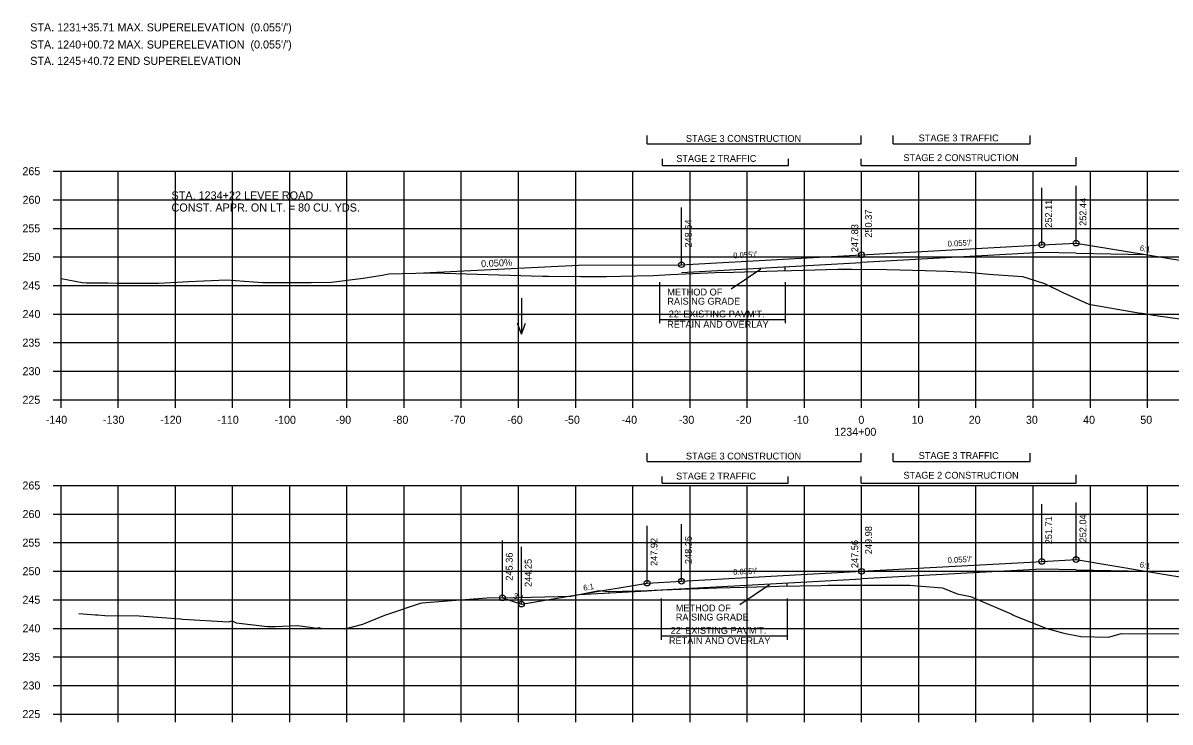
# Model space of a CAD drawing. Extents: x 1342547 to 1344156, y -1532351 to -1517216.
# Drawn here: x 1342556.2 to 1342756.8, y -1529717.5 to -1529595.1 of the extents above; entities that cross this region are included whole.
import ezdxf

# ---------------------------------------------------------------- set-up
doc = ezdxf.new("R2010")
doc.units = 0
for name, color, linetype in [('R_Alt Surface', 7, 'Continuous'), ('R_Axis', 7, 'Continuous'), ('R_Axis Annot', 7, 'Continuous'), ('R_Border Notes', 7, 'Continuous'), ('R_Draft', 7, 'Continuous'), ('R_Drive', 7, 'Continuous'), ('R_Exist Surface', 7, 'Continuous'), ('R_Fin Surface', 7, 'Continuous'), ('R_Grid', 7, 'Continuous'), ('R_No Plot', 7, 'Continuous'), ('R_Water', 7, 'Continuous'), ('R_Xsect Elev', 7, 'Continuous'), ('R_Xsect Slope', 7, 'Continuous')]:
    doc.layers.add(name, color=color, linetype=linetype)

msp = doc.modelspace()

# ---------------------------------------------------------------- linework, layer by layer
at = {"layer": 'R_Alt Surface'}
for points in [[(1342740.37, -1529635.44), (1342734.37, -1529635.32), (1342702.87, -1529637.05)], [(1342740.37, -1529635.44), (1342752.52, -1529635.68)], [(1342671.37, -1529638.79), (1342702.87, -1529637.05)], [(1342740.37, -1529690.83), (1342734.37, -1529690.71), (1342702.87, -1529692.45)], [(1342740.37, -1529690.83), (1342752.52, -1529691.08)], [(1342667.83, -1529694.37), (1342702.87, -1529692.45)], [(1342653.42, -1529695.16), (1342665.37, -1529694.51)], [(1342665.37, -1529694.51), (1342667.83, -1529694.37)]]:
    msp.add_lwpolyline(points, dxfattribs=at)
at = {"layer": 'R_Axis'}
for p, q in [((1342561.47, -1529621.09), (1342562.87, -1529621.09)), ((1342562.87, -1529661.09), (1342562.87, -1529621.09)), ((1342561.47, -1529626.09), (1342562.87, -1529626.09)), ((1342561.47, -1529631.09), (1342562.87, -1529631.09)), ((1342561.47, -1529636.09), (1342562.87, -1529636.09)), ((1342561.47, -1529641.09), (1342562.87, -1529641.09)), ((1342561.47, -1529646.09), (1342562.87, -1529646.09)), ((1342561.47, -1529651.09), (1342562.87, -1529651.09)), ((1342561.47, -1529656.09), (1342562.87, -1529656.09)), ((1342561.47, -1529661.09), (1342562.87, -1529661.09)), ((1342562.87, -1529661.09), (1342842.87, -1529661.09)), ((1342562.87, -1529662.49), (1342562.87, -1529661.09)), ((1342572.87, -1529662.49), (1342572.87, -1529661.09)), ((1342582.87, -1529662.49), (1342582.87, -1529661.09)), ((1342592.87, -1529662.49), (1342592.87, -1529661.09)), ((1342602.87, -1529662.49), (1342602.87, -1529661.09)), ((1342612.87, -1529662.49), (1342612.87, -1529661.09)), ((1342622.87, -1529662.49), (1342622.87, -1529661.09)), ((1342632.87, -1529662.49), (1342632.87, -1529661.09)), ((1342642.87, -1529662.49), (1342642.87, -1529661.09)), ((1342652.87, -1529662.49), (1342652.87, -1529661.09)), ((1342662.87, -1529662.49), (1342662.87, -1529661.09)), ((1342672.87, -1529662.49), (1342672.87, -1529661.09)), ((1342682.87, -1529662.49), (1342682.87, -1529661.09)), ((1342692.87, -1529662.49), (1342692.87, -1529661.09)), ((1342702.87, -1529662.49), (1342702.87, -1529661.09)), ((1342712.87, -1529662.49), (1342712.87, -1529661.09)), ((1342722.87, -1529662.49), (1342722.87, -1529661.09)), ((1342732.87, -1529662.49), (1342732.87, -1529661.09)), ((1342742.87, -1529662.49), (1342742.87, -1529661.09)), ((1342752.87, -1529662.49), (1342752.87, -1529661.09)), ((1342561.47, -1529676.09), (1342562.87, -1529676.09)), ((1342562.87, -1529716.09), (1342562.87, -1529676.09)), ((1342561.47, -1529681.09), (1342562.87, -1529681.09)), ((1342561.47, -1529686.09), (1342562.87, -1529686.09)), ((1342561.47, -1529691.09), (1342562.87, -1529691.09)), ((1342561.47, -1529696.09), (1342562.87, -1529696.09)), ((1342561.47, -1529701.09), (1342562.87, -1529701.09)), ((1342561.47, -1529706.09), (1342562.87, -1529706.09)), ((1342561.47, -1529711.09), (1342562.87, -1529711.09)), ((1342561.47, -1529716.09), (1342562.87, -1529716.09)), ((1342562.87, -1529716.09), (1342842.87, -1529716.09)), ((1342562.87, -1529717.49), (1342562.87, -1529716.09)), ((1342572.87, -1529717.49), (1342572.87, -1529716.09)), ((1342582.87, -1529717.49), (1342582.87, -1529716.09)), ((1342592.87, -1529717.49), (1342592.87, -1529716.09)), ((1342602.87, -1529717.49), (1342602.87, -1529716.09)), ((1342612.87, -1529717.49), (1342612.87, -1529716.09)), ((1342622.87, -1529717.49), (1342622.87, -1529716.09)), ((1342632.87, -1529717.49), (1342632.87, -1529716.09)), ((1342642.87, -1529717.49), (1342642.87, -1529716.09)), ((1342652.87, -1529717.49), (1342652.87, -1529716.09)), ((1342662.87, -1529717.49), (1342662.87, -1529716.09)), ((1342672.87, -1529717.49), (1342672.87, -1529716.09)), ((1342682.87, -1529717.49), (1342682.87, -1529716.09)), ((1342692.87, -1529717.49), (1342692.87, -1529716.09)), ((1342702.87, -1529717.49), (1342702.87, -1529716.09)), ((1342712.87, -1529717.49), (1342712.87, -1529716.09)), ((1342722.87, -1529717.49), (1342722.87, -1529716.09)), ((1342732.87, -1529717.49), (1342732.87, -1529716.09)), ((1342742.87, -1529717.49), (1342742.87, -1529716.09)), ((1342752.87, -1529717.49), (1342752.87, -1529716.09))]:
    msp.add_line(p, q, dxfattribs=at)
at = {"layer": 'R_Draft'}
for p, q in [((1342665.37, -1529616.28), (1342665.37, -1529614.85)), ((1342702.78, -1529616.28), (1342702.78, -1529614.85)), ((1342708.37, -1529616.28), (1342708.37, -1529614.85)), ((1342732.37, -1529616.28), (1342732.37, -1529614.85)), ((1342665.37, -1529616.28), (1342702.78, -1529616.28)), ((1342708.37, -1529616.28), (1342732.37, -1529616.28)), ((1342668.06, -1529620.08), (1342668.06, -1529618.93)), ((1342690.06, -1529620.08), (1342690.06, -1529618.93)), ((1342702.78, -1529620.08), (1342702.78, -1529618.93)), ((1342740.38, -1529620.08), (1342740.38, -1529618.65)), ((1342668.06, -1529620.08), (1342690.06, -1529620.08)), ((1342702.78, -1529620.08), (1342740.38, -1529620.08)), ((1342689.51, -1529638.48), (1342689.51, -1529637.79)), ((1342667.51, -1529640.51), (1342667.51, -1529647.71)), ((1342689.51, -1529640.51), (1342689.51, -1529647.71)), ((1342667.51, -1529647.04), (1342689.51, -1529647.04)), ((1342665.37, -1529671.87), (1342665.37, -1529670.44)), ((1342702.78, -1529671.87), (1342702.78, -1529670.44)), ((1342708.37, -1529671.87), (1342708.37, -1529670.44)), ((1342732.37, -1529671.87), (1342732.37, -1529670.44)), ((1342665.37, -1529671.87), (1342702.78, -1529671.87)), ((1342708.37, -1529671.87), (1342732.37, -1529671.87)), ((1342668.02, -1529675.66), (1342668.02, -1529674.52)), ((1342690.02, -1529675.66), (1342690.02, -1529674.52)), ((1342702.78, -1529675.66), (1342702.78, -1529674.52)), ((1342740.38, -1529675.66), (1342740.38, -1529674.23)), ((1342668.02, -1529675.66), (1342690.02, -1529675.66)), ((1342702.78, -1529675.66), (1342740.38, -1529675.66)), ((1342689.83, -1529693.68), (1342689.83, -1529693.16)), ((1342667.83, -1529695.89), (1342667.83, -1529703.09)), ((1342689.83, -1529695.89), (1342689.83, -1529703.09)), ((1342667.83, -1529702.41), (1342689.83, -1529702.41))]:
    msp.add_line(p, q, dxfattribs=at)
at = {"layer": 'R_Drive'}
msp.add_lwpolyline([(1342626.25, -1529638.89), (1342653.37, -1529637.52), (1342671.37, -1529637.45)], dxfattribs=at)
at = {"layer": 'R_Exist Surface'}
for points in [[(1342562.87, -1529639.85), (1342566.56, -1529640.54), (1342567.34, -1529640.61), (1342571.07, -1529640.62), (1342572.71, -1529640.67), (1342579.92, -1529640.66), (1342585.23, -1529640.39), (1342591.78, -1529640.11), (1342598.13, -1529640.57), (1342602.21, -1529640.58), (1342606.61, -1529640.59), (1342610.14, -1529640.49), (1342615.73, -1529639.81), (1342619.03, -1529639.26), (1342620.17, -1529639.04), (1342627.26, -1529638.86), (1342627.48, -1529638.86), (1342627.6, -1529638.86), (1342629.91, -1529638.93), (1342647.06, -1529639.44), (1342647.41, -1529639.45), (1342647.52, -1529639.44), (1342648.11, -1529639.45), (1342653.79, -1529639.52), (1342656.73, -1529639.52), (1342658.27, -1529639.53), (1342660.79, -1529639.47), (1342666.39, -1529639.34), (1342669.45, -1529639.19), (1342677.24, -1529638.84), (1342680.48, -1529638.74), (1342688.16, -1529638.51), (1342690.6, -1529638.45), (1342696.73, -1529638.27), (1342698.72, -1529638.24), (1342701.15, -1529638.25), (1342707.29, -1529638.31), (1342714.01, -1529638.44), (1342717.84, -1529638.59), (1342721.4, -1529638.76), (1342725.13, -1529639.11), (1342731.01, -1529639.54), (1342731.92, -1529639.82), (1342734.87, -1529640.75), (1342738.07, -1529642.31), (1342742.61, -1529644.38), (1342751.27, -1529645.85), (1342751.95, -1529645.96), (1342753.89, -1529646.28), (1342759.34, -1529647.03)], [(1342565.98, -1529698.5), (1342568.91, -1529698.71), (1342569.32, -1529698.72), (1342570.55, -1529698.86), (1342576.55, -1529698.89), (1342583.77, -1529699.45), (1342583.82, -1529699.45), (1342584.17, -1529699.48), (1342592.14, -1529699.95), (1342592.78, -1529699.78), (1342593.49, -1529700.15), (1342598.96, -1529700.77), (1342600.29, -1529700.75), (1342604.18, -1529700.62), (1342606.46, -1529700.89), (1342607.46, -1529701.04), (1342608.04, -1529700.95), (1342608.49, -1529701.19), (1342609.24, -1529701.09), (1342612.48, -1529701.17), (1342615.64, -1529700.33), (1342619.47, -1529698.76), (1342625.75, -1529696.71), (1342626.04, -1529696.6), (1342627.45, -1529696.52), (1342637.31, -1529695.77), (1342642.77, -1529695.7), (1342649.8, -1529695.54), (1342652.04, -1529695.45), (1342656.97, -1529694.48), (1342658.53, -1529694.62), (1342658.77, -1529694.67), (1342665.49, -1529694.46), (1342666.62, -1529694.43), (1342668.13, -1529694.36), (1342677.62, -1529694), (1342686.87, -1529693.75), (1342688.4, -1529693.71), (1342695.8, -1529693.57), (1342696.97, -1529693.54), (1342697.35, -1529693.54), (1342700.77, -1529693.54), (1342709.1, -1529693.53), (1342711.29, -1529693.51), (1342712.61, -1529693.65), (1342717.03, -1529694.01), (1342719.57, -1529695.06), (1342721.89, -1529695.52), (1342729.11, -1529698.63), (1342729.33, -1529698.74), (1342729.42, -1529698.78), (1342729.67, -1529698.88), (1342735.27, -1529701.12), (1342738.22, -1529701.96), (1342741.2, -1529702.54), (1342746.05, -1529702.62), (1342748.3, -1529702.02), (1342760.21, -1529702.06)]]:
    msp.add_lwpolyline(points, dxfattribs=at)
at = {"layer": 'R_Fin Surface'}
for points in [[(1342671.37, -1529637.45), (1342673.37, -1529637.34), (1342702.87, -1529635.72), (1342732.37, -1529634.1), (1342734.37, -1529633.99), (1342740.37, -1529633.66), (1342752.52, -1529635.68), (1342762.37, -1529637.32), (1342795.4, -1529648.34)], [(1342640.05, -1529695.74), (1342643.37, -1529696.84), (1342653.42, -1529695.16), (1342665.37, -1529693.17), (1342671.37, -1529692.84), (1342673.37, -1529692.73), (1342702.87, -1529691.11), (1342732.37, -1529689.49), (1342734.37, -1529689.38), (1342740.37, -1529689.05), (1342752.52, -1529691.08), (1342762.37, -1529692.72), (1342792.84, -1529702.87)]]:
    msp.add_lwpolyline(points, dxfattribs=at)
at = {"layer": 'R_Grid'}
for p, q in [((1342562.87, -1529621.09), (1342842.87, -1529621.09)), ((1342562.87, -1529661.09), (1342562.87, -1529621.09)), ((1342572.87, -1529661.09), (1342572.87, -1529621.09)), ((1342582.87, -1529661.09), (1342582.87, -1529621.09)), ((1342592.87, -1529661.09), (1342592.87, -1529621.09)), ((1342602.87, -1529661.09), (1342602.87, -1529621.09)), ((1342612.87, -1529661.09), (1342612.87, -1529621.09)), ((1342622.87, -1529661.09), (1342622.87, -1529621.09)), ((1342632.87, -1529661.09), (1342632.87, -1529621.09)), ((1342642.87, -1529661.09), (1342642.87, -1529621.09)), ((1342652.87, -1529661.09), (1342652.87, -1529621.09)), ((1342662.87, -1529661.09), (1342662.87, -1529621.09)), ((1342672.87, -1529661.09), (1342672.87, -1529621.09)), ((1342682.87, -1529661.09), (1342682.87, -1529621.09)), ((1342692.87, -1529661.09), (1342692.87, -1529621.09)), ((1342702.87, -1529661.09), (1342702.87, -1529621.09)), ((1342712.87, -1529661.09), (1342712.87, -1529621.09)), ((1342722.87, -1529661.09), (1342722.87, -1529621.09)), ((1342732.87, -1529661.09), (1342732.87, -1529621.09)), ((1342742.87, -1529661.09), (1342742.87, -1529621.09)), ((1342752.87, -1529661.09), (1342752.87, -1529621.09)), ((1342562.87, -1529626.09), (1342842.87, -1529626.09)), ((1342562.87, -1529631.09), (1342842.87, -1529631.09)), ((1342562.87, -1529636.09), (1342842.87, -1529636.09)), ((1342562.87, -1529641.09), (1342842.87, -1529641.09)), ((1342562.87, -1529646.09), (1342842.87, -1529646.09)), ((1342562.87, -1529651.09), (1342842.87, -1529651.09)), ((1342562.87, -1529656.09), (1342842.87, -1529656.09)), ((1342562.87, -1529661.09), (1342842.87, -1529661.09)), ((1342562.87, -1529676.09), (1342842.87, -1529676.09)), ((1342562.87, -1529716.09), (1342562.87, -1529676.09)), ((1342572.87, -1529716.09), (1342572.87, -1529676.09)), ((1342582.87, -1529716.09), (1342582.87, -1529676.09)), ((1342592.87, -1529716.09), (1342592.87, -1529676.09)), ((1342602.87, -1529716.09), (1342602.87, -1529676.09)), ((1342612.87, -1529716.09), (1342612.87, -1529676.09)), ((1342622.87, -1529716.09), (1342622.87, -1529676.09)), ((1342632.87, -1529716.09), (1342632.87, -1529676.09)), ((1342642.87, -1529716.09), (1342642.87, -1529676.09)), ((1342652.87, -1529716.09), (1342652.87, -1529676.09)), ((1342662.87, -1529716.09), (1342662.87, -1529676.09)), ((1342672.87, -1529716.09), (1342672.87, -1529676.09)), ((1342682.87, -1529716.09), (1342682.87, -1529676.09)), ((1342692.87, -1529716.09), (1342692.87, -1529676.09)), ((1342702.87, -1529716.09), (1342702.87, -1529676.09)), ((1342712.87, -1529716.09), (1342712.87, -1529676.09)), ((1342722.87, -1529716.09), (1342722.87, -1529676.09)), ((1342732.87, -1529716.09), (1342732.87, -1529676.09)), ((1342742.87, -1529716.09), (1342742.87, -1529676.09)), ((1342752.87, -1529716.09), (1342752.87, -1529676.09)), ((1342562.87, -1529681.09), (1342842.87, -1529681.09)), ((1342562.87, -1529686.09), (1342842.87, -1529686.09)), ((1342562.87, -1529691.09), (1342842.87, -1529691.09)), ((1342562.87, -1529696.09), (1342842.87, -1529696.09)), ((1342562.87, -1529701.09), (1342842.87, -1529701.09)), ((1342562.87, -1529706.09), (1342842.87, -1529706.09)), ((1342562.87, -1529711.09), (1342842.87, -1529711.09)), ((1342562.87, -1529716.09), (1342842.87, -1529716.09))]:
    msp.add_line(p, q, dxfattribs=at)
at = {"layer": 'R_No Plot'}
for centre in [(1342734.37, -1529633.99), (1342740.37, -1529633.66), (1342671.37, -1529637.45), (1342702.87, -1529635.72), (1342734.37, -1529689.38), (1342740.37, -1529689.05), (1342702.87, -1529691.11), (1342665.37, -1529693.17), (1342671.37, -1529692.84), (1342640.05, -1529695.74), (1342643.37, -1529696.84)]:
    msp.add_circle(centre, 0.5, dxfattribs=at)
at = {"layer": 'R_Water'}
for p, q in [((1342643.42, -1529643.33), (1342643.42, -1529649.62)), ((1342643.42, -1529649.62), (1342642.72, -1529647.69)), ((1342643.42, -1529649.62), (1342644.12, -1529647.69))]:
    msp.add_line(p, q, dxfattribs=at)
at = {"layer": 'R_Xsect Elev'}
for p, q in [((1342734.37, -1529633.99), (1342734.37, -1529623.99)), ((1342740.37, -1529633.66), (1342740.37, -1529623.66)), ((1342702.87, -1529635.72), (1342702.87, -1529625.72)), ((1342671.37, -1529637.45), (1342671.37, -1529627.45)), ((1342702.87, -1529638.26), (1342702.87, -1529628.26)), ((1342685.26, -1529638.22), (1342680.06, -1529641.71)), ((1342740.37, -1529689.05), (1342740.37, -1529679.05)), ((1342702.87, -1529691.11), (1342702.87, -1529681.11)), ((1342734.37, -1529689.38), (1342734.37, -1529679.38)), ((1342671.37, -1529692.84), (1342671.37, -1529682.84)), ((1342665.37, -1529693.17), (1342665.37, -1529683.17)), ((1342702.87, -1529693.54), (1342702.87, -1529683.54)), ((1342640.05, -1529695.74), (1342640.05, -1529685.74)), ((1342643.37, -1529696.84), (1342643.37, -1529686.84)), ((1342686.75, -1529693.5), (1342681.55, -1529696.98))]:
    msp.add_line(p, q, dxfattribs=at)

# ---------------------------------------------------------------- texts
at = {"layer": 'R_Axis Annot'}
for s, p in [('265', (1342556.12, -1529621.79)), ('260', (1342556.14, -1529626.79)), ('255', (1342556.12, -1529631.79)), ('250', (1342556.14, -1529636.79)), ('245', (1342556.12, -1529641.79)), ('240', (1342556.14, -1529646.79)), ('235', (1342556.12, -1529651.79)), ('230', (1342556.14, -1529656.79)), ('225', (1342556.12, -1529661.79)), ('-140', (1342560.2, -1529665.29)), ('-130', (1342570.2, -1529665.29)), ('-120', (1342580.2, -1529665.29)), ('-110', (1342590.2, -1529665.29)), ('-100', (1342600.2, -1529665.29)), ('-90', (1342610.9, -1529665.29)), ('-80', (1342620.9, -1529665.29)), ('-70', (1342630.9, -1529665.29)), ('-60', (1342640.9, -1529665.29)), ('-50', (1342650.9, -1529665.29)), ('-40', (1342660.9, -1529665.29)), ('-30', (1342670.9, -1529665.29)), ('-20', (1342680.9, -1529665.29)), ('-10', (1342690.9, -1529665.29)), ('0', (1342702.3, -1529665.29)), ('10', (1342711.6, -1529665.29)), ('20', (1342721.6, -1529665.29)), ('30', (1342731.6, -1529665.29)), ('40', (1342741.6, -1529665.29)), ('50', (1342751.6, -1529665.29)), ('1234+00', (1342698.1, -1529667.39)), ('265', (1342556.12, -1529676.79)), ('260', (1342556.14, -1529681.79)), ('255', (1342556.12, -1529686.79)), ('250', (1342556.14, -1529691.79)), ('245', (1342556.12, -1529696.79)), ('240', (1342556.14, -1529701.79)), ('235', (1342556.12, -1529706.79)), ('230', (1342556.14, -1529711.79)), ('225', (1342556.12, -1529716.79))]:
    msp.add_text(s, height=1.4, dxfattribs=at).set_placement(p)
at = {"layer": 'R_Border Notes'}
for s, height, p in [("STA. 1231+35.71 MAX. SUPERELEVATION  (0.055'/')", 1.41, (1342557.48, -1529596.62)), ("STA. 1240+00.72 MAX. SUPERELEVATION  (0.055'/')", 1.41, (1342557.48, -1529599.62)), ('STA. 1245+40.72 END SUPERELEVATION', 1.41, (1342557.48, -1529602.48)), ('STA. 1234+22 LEVEE ROAD', 1.4147, (1342582.19, -1529626.03)), ('CONST. APPR. ON LT. = 80 CU. YDS.', 1.4147, (1342582.19, -1529628.15))]:
    msp.add_text(s, height=height, dxfattribs=at).set_placement(p)
at = {"layer": 'R_Draft'}
for s, p in [('STAGE 3 CONSTRUCTION', (1342672.14, -1529615.96)), ('STAGE 3 TRAFFIC', (1342712.85, -1529615.87)), ('STAGE 2 TRAFFIC', (1342670.46, -1529619.45)), ('STAGE 2 CONSTRUCTION', (1342710.18, -1529619.32)), ("22' EXISTING PAVM'T.", (1342669.15, -1529646.67)), ('RETAIN AND OVERLAY', (1342668.86, -1529648.47)), ('STAGE 3 CONSTRUCTION', (1342672.14, -1529671.54)), ('STAGE 3 TRAFFIC', (1342712.85, -1529671.45)), ('STAGE 2 TRAFFIC', (1342670.42, -1529675.04)), ('STAGE 2 CONSTRUCTION', (1342710.18, -1529674.9)), ("22' EXISTING PAVM'T.", (1342669.47, -1529702.05)), ('RETAIN AND OVERLAY', (1342669.17, -1529703.85))]:
    msp.add_text(s, height=1.2, dxfattribs=at).set_placement(p)
at = {"layer": 'R_Xsect Elev'}
for s, rotation, p in [('252.11', 90, (1342736.17, -1529630.99)), ('252.44', 90, (1342742.17, -1529630.66)), ('250.37', 90, (1342704.67, -1529632.72)), ('248.64', 90, (1342673.17, -1529634.45)), ('247.83', 90, (1342702.27, -1529635.26)), ('0.050%', 2.8772, (1342636.35, -1529637.9)), ('251.71', 90, (1342736.17, -1529686.38)), ('252.04', 90, (1342742.17, -1529686.05)), ('248.25', 90, (1342673.17, -1529689.84)), ('249.98', 90, (1342704.67, -1529688.11)), ('247.92', 90, (1342667.17, -1529690.17)), ('247.56', 90, (1342702.27, -1529690.54)), ('245.36', 90, (1342641.85, -1529692.74)), ('244.25', 90, (1342645.17, -1529693.84))]:
    msp.add_text(s, height=1.2, rotation=rotation, dxfattribs=at).set_placement(p)
for s, p in [('METHOD OF', (1342668.89, -1529642.84)), ('RAISING GRADE', (1342668.89, -1529644.44)), ('METHOD OF', (1342670.37, -1529698.12)), ('RAISING GRADE', (1342670.37, -1529699.72))]:
    msp.add_text(s, height=1.2, dxfattribs=at).set_placement(p)
at = {"layer": 'R_Xsect Slope'}
for s, rotation, p in [("0.055'/'", 3.1481, (1342717.94, -1529634.29)), ('6:1', 350.5377, (1342751.45, -1529635)), ("0.055'/'", 3.1481, (1342680.44, -1529636.35)), ("0.055'/'", 3.1481, (1342717.94, -1529689.68)), ("0.055'/'", 3.1481, (1342680.44, -1529691.74)), ('6:1', 350.5377, (1342751.45, -1529690.39)), ('3:1', 341.5651, (1342641.86, -1529695.81)), ('6:1', 9.4623, (1342654.28, -1529694.51))]:
    msp.add_text(s, height=1, rotation=rotation, dxfattribs=at).set_placement(p)

doc.saveas('drawing.dxf')
